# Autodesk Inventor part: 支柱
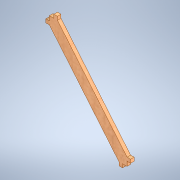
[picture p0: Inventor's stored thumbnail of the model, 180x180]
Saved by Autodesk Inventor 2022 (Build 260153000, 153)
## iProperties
Created: 2024-12
Part Number: 支柱
Material: MDF 中密度繊維ボード
Document SubType Name: Modeling
Designer: shimizu
Density: 0.8 g/cm^3
Appearance: サクラ材 - ナチュラル 抑えた光沢
Author: shimizu
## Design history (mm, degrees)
sketch "スケッチ1"
  geometry: L1 (-30.797, 30.211)-(-25.116, 30.211); L2 (-25.116, 30.211)-(-25.116, 24.53); L3 (-25.116, 24.53)-(-30.797, 24.53); L4 (-30.797, 24.53)-(-30.797, 30.211); L5 (18.522, -29.109)-(24.203, -29.109); L6 (24.203, -29.109)-(24.203, -34.789); L7 (24.203, -34.789)-(18.522, -34.789); L8 (18.522, -34.789)-(18.522, -29.109); L9 (-30.797, 24.53)-(18.522, -34.789); L10 (-25.116, 30.211)-(24.203, -29.109); L11 (-30.797, 24.53)-(-33.297, 24.53); L12 (-33.297, 24.53)-(-33.297, 27.03); L13 (-33.297, 27.03)-(-30.797, 27.03); L14 (-30.797, 27.03)-(-30.797, 24.53); L15 (-25.116, 30.211)-(-27.616, 30.211); L16 (-27.616, 30.211)-(-27.616, 32.711); L17 (-27.616, 32.711)-(-25.116, 32.711); L18 (-25.116, 32.711)-(-25.116, 30.211); L19 (18.522, -34.789)-(21.022, -34.789); L20 (21.022, -34.789)-(21.022, -37.289); L21 (21.022, -37.289)-(18.522, -37.289); L22 (18.522, -37.289)-(18.522, -34.789); L23 (24.203, -29.109)-(26.703, -29.109); L24 (26.703, -29.109)-(26.703, -31.609); L25 (26.703, -31.609)-(24.203, -31.609); L26 (24.203, -31.609)-(24.203, -29.109); 5 further points
  constraints: 52 end point, 13 parallel, 8 perpendicular, 6 horizontal
  dimensions: "d0" = 8 distance between parallel lines of L9 L10; "d1" = 55 distance between parallel lines of L6 L4; "d2" = 65 distance between parallel lines of L7 L1; "d3" = 2.5 distance of L11.end L12.end; "d4" = 2.5 distance of L3.end L11.end; "d5" = 2.5 distance of L17.end L1.end; "d6" = 2.5 distance of L16.end L17.end; "d7" = 2.5 distance of L21.end L7.end; "d8" = 2.5 distance of L20.end L21.end; "d9" = 2.5 distance of L23.end L24.end; "d10" = 2.5 distance of L5.end L23.end
extrude "押し出し1" new body sketch "スケッチ1" distance "d11" = 2.5; taper "d12" = 0 deg
node "ソリッド1"
